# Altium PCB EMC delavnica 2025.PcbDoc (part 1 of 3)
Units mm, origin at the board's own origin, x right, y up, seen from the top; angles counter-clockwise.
Board outline 146.35 x 55.01 mm, 2 copper layers (Top Layer, Bottom Layer), stack 1.671 mm thick; 5 components, 5 nets, 32 pads, 0 vias.
Unrouted connection lines stored in the file: 7.
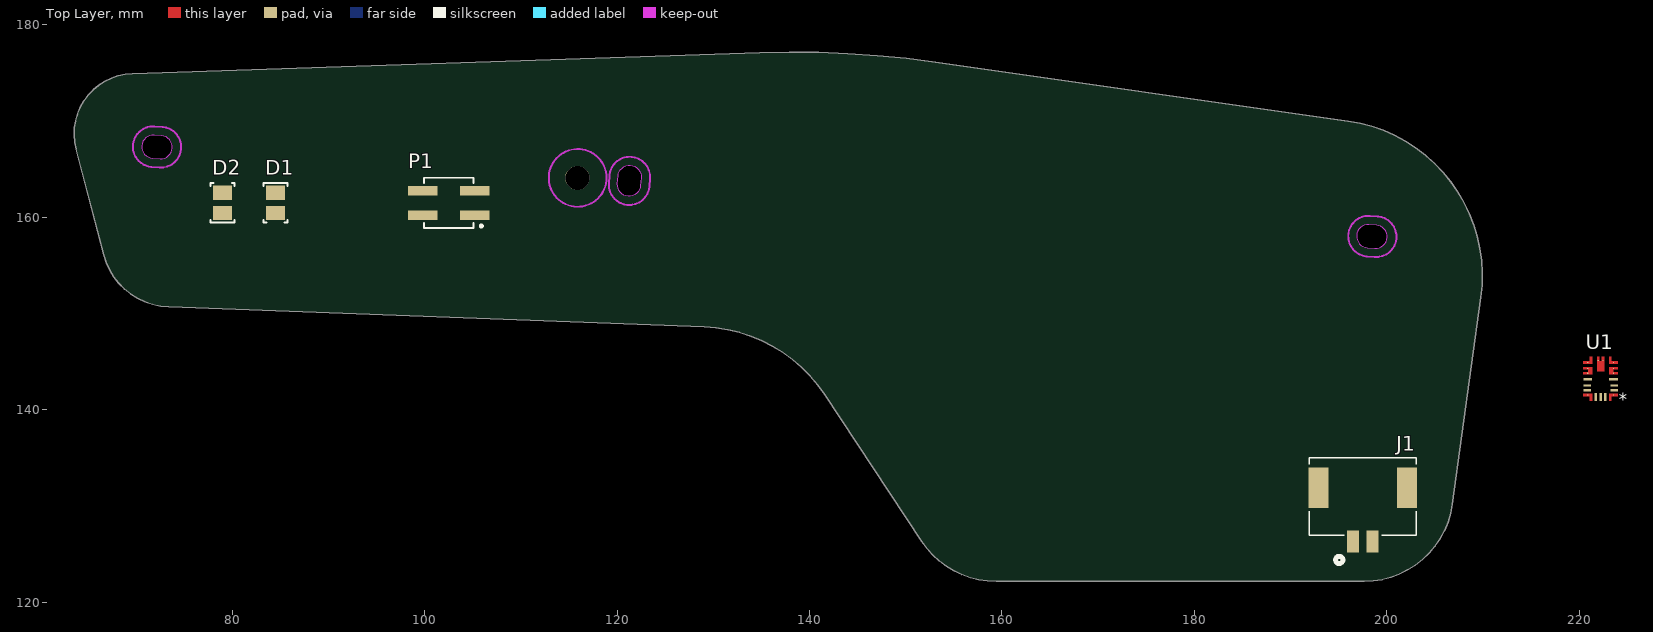
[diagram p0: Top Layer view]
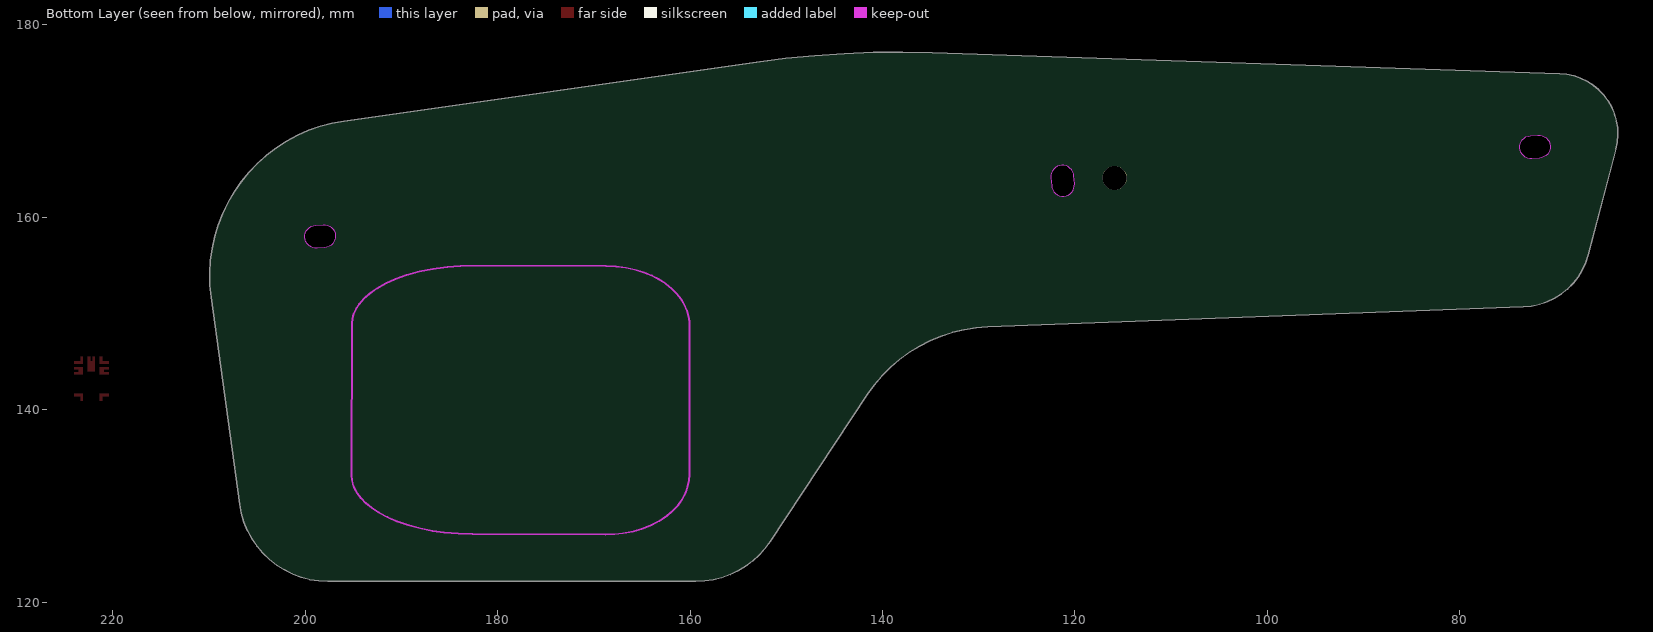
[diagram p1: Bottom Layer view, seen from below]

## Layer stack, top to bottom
Top Solder: solder mask 0.0102, Solder Resist, Dk 3.5
Top Layer: signal copper 0.0356
Dielectric 1: dielectric 1.6, FR-4, Dk 4.8
Bottom Layer: signal copper 0.0356
Bottom Solder: solder mask 0.0102, Solder Resist, Dk 3.5

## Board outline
206.643,163.698 207.369,162.652 208.011,161.552 208.565,160.406 209.028,159.22 209.397,158.001 209.669,156.756 209.843,155.495 209.918,154.224 209.893,152.95 209.769,151.683 206.805,130.172 206.627,129.24 206.355,128.331 205.992,127.454 205.541,126.619 205.007,125.835 204.395,125.109 203.713,124.45 202.966,123.864 202.164,123.357 201.314,122.935 200.425,122.602 199.507,122.361 198.57,122.216 197.622,122.168 159.391,122.166 158.478,122.211 157.574,122.346 156.688,122.57 155.827,122.879 155.002,123.272 154.219,123.744 153.486,124.291 152.811,124.907 152.2,125.587 151.659,126.324 141.581,141.568 140.854,142.578 140.05,143.527 139.173,144.41 138.229,145.221 137.224,145.954 136.165,146.606 135.057,147.173 133.907,147.649 132.724,148.034 131.514,148.324 130.285,148.517 129.044,148.613 73.404,150.685 72.564,150.765 71.74,150.942 70.941,151.214 70.179,151.576 69.465,152.023 68.807,152.551 68.214,153.151 67.695,153.816 67.257,154.537 66.905,155.303 66.644,156.105 66.643,156.106 63.769,167.074 63.622,167.809 63.565,168.556 63.597,169.305 63.718,170.044 63.926,170.764 64.219,171.454 64.592,172.104 65.039,172.705 65.556,173.248 66.133,173.725 66.763,174.131 67.437,174.458 68.146,174.702 68.878,174.861 69.624,174.93 69.625,174.93 134.849,177.12 137.897,177.177 140.945,177.145 143.991,177.025 147.032,176.816 150.065,176.518 153.089,176.131 195.951,170.01 197.204,169.781 198.435,169.454 199.637,169.033 200.801,168.518 201.923,167.914 202.993,167.224 204.006,166.453 204.956,165.604 205.837,164.684
cut-out: 122.492,164.129 122.431,163.301 122.391,163.07 122.306,162.85 122.18,162.652 122.018,162.482 121.826,162.346 121.611,162.251 121.382,162.2 121.147,162.194 120.915,162.234 120.696,162.318 120.497,162.444 120.327,162.606 120.191,162.798 120.096,163.013 120.044,163.242 120.038,163.477 120.099,164.305 120.139,164.537 120.224,164.756 120.35,164.955 120.512,165.125 120.704,165.26 120.919,165.356 121.149,165.407 121.384,165.413 121.615,165.373 121.835,165.288 122.033,165.163 122.204,165.001 122.339,164.808 122.435,164.594 122.486,164.364
cut-out: 198.133,159.247 197.898,159.241 197.669,159.189 197.454,159.093 197.262,158.958 197.1,158.787 196.975,158.588 196.89,158.369 196.85,158.137 196.856,157.902 196.908,157.673 197.003,157.458 197.139,157.266 197.309,157.104 197.508,156.978 197.727,156.893 197.959,156.853 198.756,156.795 198.991,156.801 199.221,156.853 199.436,156.948 199.628,157.084 199.789,157.255 199.915,157.453 199.999,157.673 200.039,157.904 200.034,158.139 199.982,158.369 199.886,158.584 199.751,158.776 199.581,158.938 199.382,159.064 199.163,159.148 198.931,159.189
cut-out: 73.325,168.232 73.126,168.358 72.907,168.443 72.676,168.483 71.878,168.541 71.643,168.535 71.413,168.483 71.199,168.388 71.006,168.252 70.845,168.082 70.719,167.883 70.635,167.663 70.595,167.432 70.601,167.197 70.652,166.967 70.748,166.752 70.883,166.56 71.053,166.398 71.252,166.272 71.471,166.188 71.703,166.148 72.501,166.089 72.736,166.095 72.965,166.147 73.18,166.243 73.372,166.379 73.534,166.549 73.659,166.748 73.744,166.967 73.784,167.199 73.778,167.434 73.726,167.663 73.631,167.878 73.495,168.07

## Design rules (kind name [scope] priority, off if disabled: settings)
Clearance [All] p1: gap=0.2 ignorepadtopadclearanceinfootprint=FALSE
ComponentClearance [All] p1: gap=0.254 collisioncheckmode=3 verticalgap=0.5 showdistances=FALSE donotcheckwithout3dbody=TRUE
Height [All] p1: minheight=0 maxheight=9.3 prefheight=9
PlaneConnect [All] p1: pad.planeconnectstyle=Relief pad.reliefexpansion=0.508 pad.reliefentries=4 pad.reliefconductorwidth=0.254 pad.reliefairgap=0.254 via.planeconnectstyle=Direct via.reliefexpansion=0.508 via.reliefentries=4 via.reliefconductorwidth=0.254 via.reliefairgap=0.254
PolygonConnect [All] p1: thpad.connectstyle=Relief thpad.reliefconductorwidth=0.254 thpad.reliefentries=4 thpad.polygonreliefangle="90 Angle" thpad.airgapwidth=0.254 smdpad.connectstyle=Relief smdpad.reliefconductorwidth=0.254 smdpad.reliefentries=4 smdpad.polygonreliefangle="90 Angle" smdpad.airgapwidth=0.254 via.connectstyle=Direct via.reliefconductorwidth=0.254 via.reliefentries=4 via.polygonreliefangle="90 Angle" via.airgapwidth=0.254
RoutingVias [All] p1: holewidth=0.4 width=0.7 viastyle="Through Hole" minholewidth=0.3 minwidth=0.6 maxholewidth=0.5 maxwidth=0.8
SolderMaskExpansion [All] p1: expansion=0.102 istentingtop=FALSE
SupplyNets "Schematic Supply Nets_1" [InNet('GND')] p1: voltage=0.000
SupplyNets "Schematic Supply Nets" [InNet('Vin')] p2: voltage=0.000
Width [All] p1: maxlimit=5 minlimit=0.2 preferedwidth=0.3
27 further rules are at their usual default settings.

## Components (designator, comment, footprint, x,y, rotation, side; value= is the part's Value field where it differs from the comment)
D1 "NFSW123" NFSW123G 84.5,161.5 r270 top locked value={Value}
D2 "NFSW123" NFSW123G 79,161.5 r90 top locked value={Value}
J1 "5023520200" CONN02_502352_MOL 197.5,131 r180 top locked
P1 "61000421121" 61000421121 102.5,161.5 r90 top locked
U1 "MPQ7200AGLE-AEC1-P" QFN-19_MPQ7200A_MNP 222.213,143.225 r180 top

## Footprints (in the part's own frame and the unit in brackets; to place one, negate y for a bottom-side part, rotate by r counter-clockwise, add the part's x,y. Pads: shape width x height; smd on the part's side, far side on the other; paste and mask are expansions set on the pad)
61000421121 [mm] "Pin Header, pitch 2.54 mm, SMD, Vertical, dual row, 4p"
  rect 1x3.1 smd: 1(-1.27,-2.7) 2(-1.27,2.7) 3(1.27,-2.7) 4(1.27,2.7)
  silkscreen extent -2.62,-3.53 2.62,2.57, body extent -2.54,-3.75 2.54,3.75, height 9.62
CONN02_502352_MOL [mil]
  rect 49x89 smd paste+0 mask+0: 1(39.37,184.21) 2(-39.37,184.21)
  rect 81x167 smd paste-83.5 mask-83.5: 3(-181.1,-35.48) 4(181.1,-35.48)
  silkscreen extent -220,-158 220,275, body extent -215,-156 215,204, height 315
NFSW123G [mm]
  rect 1.5x2 smd: A(1.05,0) K(-1.05,0)
  silkscreen extent -2.05,-1.25 2.05,1.25, body extent -1.5,-1 1.5,1, height 0.71
QFN-19_MPQ7200A_MNP [mm]
  rect 0.127x0.127 smd paste-0.064 mask-0.064: 1(-1.337,1.7) 5(-1.337,-0.575) 6(-1.337,-1.075) 7(-1.337,-1.7) 8(-0.25,-1.9) 9(0.25,-1.9) 10(1.337,-1.7) 11(1.337,-1.075) 12(1.337,-0.575) 16(1.337,1.7)
  rect 0.8x0.25 smd paste+0 mask+0: 2(-1.4,1.2) 3(-1.4,0.7) 14(1.4,0.7) 15(1.4,1.2)
  rect 0.925x0.25 smd paste+0 mask+0: 4(-1.337,0.05) 13(1.337,0.05)
  rect 0.25x0.8 smd paste+0 mask+0: 17(0.5,1.9) 18(0,1.9) 19(-0.5,1.9)
  Top Layer region: -1.125,-1.825 -1.799,-1.825 -1.799,-1.575 -0.874,-1.575 -0.875,-2.3 -1.125,-2.3
  Top Layer region: 0.874,-0.475 1.799,-0.475 1.799,-0.675 1.299,-0.675 1.299,-0.975 1.799,-0.975 1.799,-1.175 0.874,-1.175
  Top Layer region: 1.125,1.825 1.799,1.825 1.799,1.575 0.874,1.575 0.875,2.3 1.125,2.3
  Top Layer region: 1.125,-1.825 1.799,-1.825 1.799,-1.575 0.874,-1.575 0.875,-2.3 1.125,-2.3
  Top Layer region: -1.125,1.825 -1.799,1.825 -1.799,1.575 -0.874,1.575 -0.875,2.3 -1.125,2.3
  Top Layer region: -0.874,-0.475 -1.799,-0.475 -1.799,-0.675 -1.299,-0.675 -1.299,-0.975 -1.799,-0.975 -1.799,-1.175 -0.874,-1.175
  Top Layer region: -0.125,-2.3 -0.375,-2.3 -0.375,-0.8 0.375,-0.8 0.375,-2.3 0.125,-2.3 0.125,-1.8 -0.125,-1.8
  body extent -1.5,-2 1.5,2, height 0.85

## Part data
D1 D2: "Chip LED diode"
J1: "No Description Available", Mfr_Name="Molex Connector Corporation"
P1: library part CMP-1502-01021-3, Color=Black, Contact Resistance=20mΩ, Current Rating=3A, Operating Supply Voltage=250V
U1: "No Description Available", Mfr_Name="Monolithic Power Systems"

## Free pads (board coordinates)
  round 2.5 hole 2.5 unplated: 1(115.871,164.1)

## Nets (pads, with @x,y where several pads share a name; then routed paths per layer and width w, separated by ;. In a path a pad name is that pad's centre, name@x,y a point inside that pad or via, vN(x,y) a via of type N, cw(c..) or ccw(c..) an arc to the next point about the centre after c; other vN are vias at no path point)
GND: D2.K J1.2 J1.3 J1.4
NetD1_A: D1.A P1.2 P1.4
NetD1_K: D1.K D2.A
NetP1_1: P1.1 P1.3
Vin: J1.1
pads on no net: U1.1 U1.2 U1.3 U1.4 U1.5 U1.6 U1.7 U1.8 U1.9 U1.10 U1.11 U1.12 U1.13 U1.14 U1.15 U1.16 U1.17 U1.18 U1.19

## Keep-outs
Top Layer:
  circle w0.2: c115.9,164.1 r3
